// Mitsubishi GX Works2 project: school_ver0901   PLC: FX3S

PROGRAM MAIN
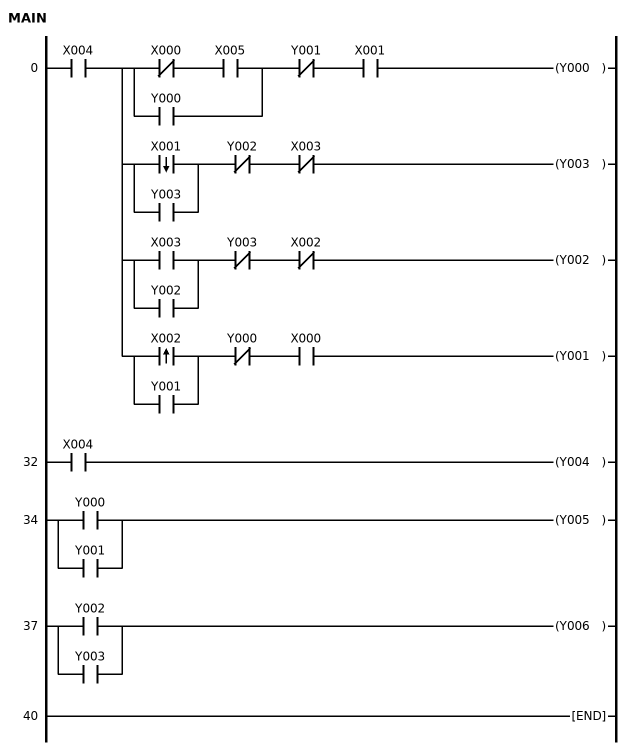
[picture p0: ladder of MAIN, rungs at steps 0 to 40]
0     LD      X004
      MPS
      LDI     X000
      AND     X005
      OR      Y000
      ANB
      ANI     Y001
      AND     X001
      OUT     Y000
      MRD
      LDF     X001
      OR      Y003
      ANB
      ANI     Y002
      ANI     X003
      OUT     Y003
      MRD
      LD      X003
      OR      Y002
      ANB
      ANI     Y003
      ANI     X002
      OUT     Y002
      MPP
      LDP     X002
      OR      Y001
      ANB
      ANI     Y000
      AND     X000
      OUT     Y001
32    LD      X004
      OUT     Y004
34    LD      Y000
      OR      Y001
      OUT     Y005
37    LD      Y002
      OR      Y003
      OUT     Y006
40    END
END_PROGRAM
